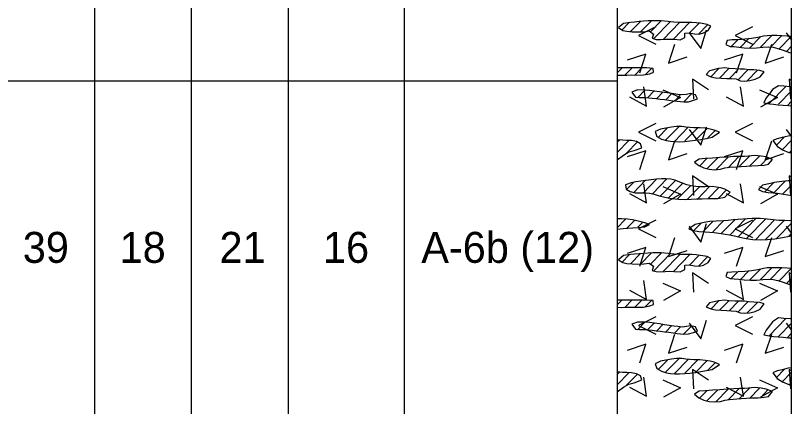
# Model space of a CAD drawing. Extents: x -0.01 to 0.83, y -0.63 to 1.27.
# Drawn here: x 0.6664 to 0.8333, y 0.5756 to 0.6598 of the extents above; entities that cross this region are included whole.
import ezdxf

# ---------------------------------------------------------------- set-up
doc = ezdxf.new("R2010")
doc.units = 0

msp = doc.modelspace()

# ---------------------------------------------------------------- linework, layer by layer
for points in [[(0, 0), (0.83333, 0), (0.83333, 1.275), (0, 1.275)], [(0, 0), (0.83333, 0), (0.83333, 1.275), (0, 1.275)], [(0, 0), (0.83333, 0), (0.83333, 1.275), (0, 1.275)], [(0, 0), (0.83333, 0), (0.83333, 1.275), (0, 1.275)], [(0, 0), (0.83333, 0), (0.83333, 1.275), (0, 1.275)], [(0.79708, 0.65659), (0.79794, 0.65641), (0.79904, 0.6563), (0.80028, 0.65627), (0.80156, 0.65632), (0.80274, 0.65648), (0.80361, 0.65582), (0.80338, 0.65492), (0.80422, 0.65465), (0.80517, 0.65463), (0.80613, 0.65469), (0.8072, 0.65472), (0.80818, 0.65469), (0.80939, 0.65461), (0.81037, 0.65508), (0.81038, 0.65603), (0.8113, 0.65609), (0.81244, 0.6559), (0.81346, 0.65579), (0.81438, 0.65605), (0.81539, 0.65659), (0.81601, 0.6575), (0.81517, 0.65788), (0.81374, 0.65815), (0.81285, 0.65825), (0.81187, 0.65831), (0.81, 0.65831), (0.8091, 0.65833), (0.808, 0.6584), (0.80678, 0.65856), (0.8053, 0.65869), (0.80443, 0.6587), (0.80349, 0.65868), (0.80251, 0.65864), (0.80152, 0.65858), (0.80054, 0.6585), (0.79959, 0.65841), (0.7987, 0.65831), (0.79722, 0.65809), (0.79614, 0.65721)], [(0.83241, 0.65537), (0.83129, 0.65544), (0.83017, 0.65548), (0.8291, 0.65548), (0.82811, 0.65544), (0.82728, 0.65535), (0.82608, 0.65505), (0.82476, 0.65483), (0.8233, 0.65469), (0.82183, 0.65461), (0.82051, 0.65455), (0.81951, 0.65445), (0.81922, 0.65358), (0.82013, 0.65316), (0.82097, 0.65311), (0.822, 0.65301), (0.82318, 0.65288), (0.82448, 0.6528), (0.82584, 0.65282), (0.82719, 0.65298), (0.82836, 0.65305), (0.8294, 0.65297), (0.83043, 0.65274), (0.83156, 0.65235), (0.83291, 0.65186), (0.83333, 0.65178), (0.83333, 0.6553)], [(0.79583, 0.64696), (0.79676, 0.64695), (0.79792, 0.64697), (0.79882, 0.64701), (0.79992, 0.64697), (0.80151, 0.64701), (0.80282, 0.64727), (0.80367, 0.64759), (0.80354, 0.64843), (0.80216, 0.64851), (0.79583, 0.64851)], [(0.81822, 0.64632), (0.81944, 0.64626), (0.82033, 0.64622), (0.82145, 0.64615), (0.82229, 0.64574), (0.82324, 0.64569), (0.82438, 0.6458), (0.82555, 0.64608), (0.82662, 0.64659), (0.82749, 0.64769), (0.82651, 0.64799), (0.82524, 0.64809), (0.82413, 0.64815), (0.82324, 0.64826), (0.82226, 0.64828), (0.82121, 0.6483), (0.81995, 0.64839), (0.81902, 0.64851), (0.81761, 0.64837), (0.81566, 0.64793), (0.81496, 0.64709), (0.81598, 0.6466), (0.81695, 0.64642)], [(0.83305, 0.64446), (0.83171, 0.64457), (0.83054, 0.64467), (0.82925, 0.64385), (0.82857, 0.64294), (0.82792, 0.64205), (0.82735, 0.64103), (0.82858, 0.6408), (0.82945, 0.6407), (0.83045, 0.6406), (0.83155, 0.64051), (0.83272, 0.64041), (0.83333, 0.64036), (0.83333, 0.64445)], [(0.80066, 0.64216), (0.80188, 0.64215), (0.80339, 0.64202), (0.80423, 0.64193), (0.8051, 0.64182), (0.806, 0.6417), (0.80692, 0.64158), (0.80784, 0.64146), (0.80875, 0.64135), (0.81014, 0.64121), (0.81119, 0.64122), (0.81222, 0.64157), (0.81308, 0.64185), (0.81267, 0.64275), (0.8116, 0.643), (0.81075, 0.6428), (0.80989, 0.64272), (0.80885, 0.6428), (0.80799, 0.64291), (0.80703, 0.64306), (0.806, 0.64322), (0.80492, 0.64339), (0.80384, 0.64354), (0.8028, 0.64367), (0.80182, 0.64377), (0.8002, 0.64378), (0.79901, 0.6433), (0.79974, 0.64226)], [(0.81233, 0.63565), (0.81063, 0.63577), (0.80977, 0.63591), (0.8086, 0.63591), (0.80755, 0.63577), (0.80632, 0.63557), (0.80513, 0.63533), (0.80403, 0.63481), (0.80436, 0.63375), (0.80536, 0.63318), (0.80647, 0.63288), (0.8073, 0.63273), (0.80824, 0.63265), (0.80926, 0.63264), (0.81035, 0.63269), (0.81149, 0.6328), (0.81267, 0.63294), (0.81386, 0.63313), (0.81506, 0.63334), (0.81625, 0.63358), (0.81783, 0.63466), (0.81673, 0.63515), (0.81585, 0.63536), (0.8148, 0.63552), (0.81361, 0.63562)], [(0.79583, 0.62875), (0.79719, 0.62974), (0.79831, 0.63044), (0.79951, 0.63071), (0.80111, 0.63131), (0.80086, 0.63219), (0.80002, 0.63267), (0.79889, 0.63286), (0.79791, 0.63289), (0.79694, 0.63295), (0.79583, 0.63303)], [(0.83265, 0.63384), (0.83136, 0.63353), (0.83028, 0.63326), (0.82934, 0.63286), (0.83026, 0.63166), (0.83142, 0.6309), (0.83279, 0.63032), (0.83333, 0.63022), (0.83333, 0.63393)], [(0.82537, 0.62969), (0.82408, 0.62954), (0.82319, 0.62948), (0.82214, 0.62946), (0.82091, 0.62942), (0.81947, 0.62933), (0.81792, 0.62921), (0.81632, 0.62909), (0.81475, 0.629), (0.81348, 0.62889), (0.81247, 0.62825), (0.81337, 0.62749), (0.81444, 0.62699), (0.81561, 0.6267), (0.81675, 0.6266), (0.81807, 0.62671), (0.81896, 0.62698), (0.82003, 0.62713), (0.82157, 0.62725), (0.82253, 0.62731), (0.82362, 0.62737), (0.82483, 0.62743), (0.82618, 0.62749), (0.82745, 0.6276), (0.82842, 0.62778), (0.82927, 0.62883), (0.82791, 0.62935), (0.82679, 0.62955)], [(0.79885, 0.62378), (0.79763, 0.62332), (0.79773, 0.62242), (0.79859, 0.6219), (0.7997, 0.6216), (0.80074, 0.62161), (0.80165, 0.62163), (0.80281, 0.62154), (0.80377, 0.62134), (0.80486, 0.62099), (0.80606, 0.62069), (0.80751, 0.62042), (0.80905, 0.62023), (0.81052, 0.6202), (0.81177, 0.62026), (0.81289, 0.6203), (0.81408, 0.62033), (0.81553, 0.62037), (0.81642, 0.6204), (0.81745, 0.62043), (0.81897, 0.6207), (0.82011, 0.62174), (0.81896, 0.62241), (0.8181, 0.62268), (0.81717, 0.62287), (0.81626, 0.62298), (0.81479, 0.62292), (0.81343, 0.62292), (0.8121, 0.62307), (0.8108, 0.62337), (0.80953, 0.62383), (0.8082, 0.62438), (0.80736, 0.62454), (0.8064, 0.62462), (0.80536, 0.62462), (0.80427, 0.62456), (0.80314, 0.62445), (0.80201, 0.62431), (0.8009, 0.62414), (0.79984, 0.62396)], [(0.83263, 0.62423), (0.83126, 0.62409), (0.82969, 0.62382), (0.82883, 0.62365), (0.82712, 0.62324), (0.82623, 0.62237), (0.82708, 0.62188), (0.82831, 0.62169), (0.82941, 0.62163), (0.83033, 0.62154), (0.83165, 0.62135), (0.83253, 0.62121), (0.83333, 0.62107), (0.83333, 0.62422)], [(0.82816, 0.61157), (0.82978, 0.61174), (0.83137, 0.612), (0.8329, 0.61231), (0.83333, 0.61241), (0.83333, 0.61565), (0.83295, 0.61562), (0.83188, 0.61564), (0.83071, 0.61569), (0.82938, 0.6158), (0.82807, 0.61597), (0.82662, 0.61608), (0.82576, 0.61609), (0.82484, 0.61606), (0.82387, 0.61601), (0.82286, 0.61594), (0.82182, 0.61586), (0.82077, 0.61578), (0.81973, 0.61569), (0.81872, 0.61562), (0.81715, 0.61552), (0.81579, 0.61543), (0.81491, 0.6153), (0.81357, 0.61502), (0.8126, 0.61481), (0.81121, 0.61389), (0.8121, 0.61353), (0.81345, 0.61328), (0.81479, 0.61319), (0.81668, 0.61309), (0.81818, 0.61289), (0.81905, 0.61275), (0.82, 0.61257), (0.82107, 0.61235), (0.82225, 0.6121), (0.82357, 0.61181), (0.82501, 0.61158), (0.82656, 0.61151)], [(0.79583, 0.61382), (0.79715, 0.61393), (0.79814, 0.61401), (0.79922, 0.61408), (0.80039, 0.61417), (0.80179, 0.61429), (0.80275, 0.6148), (0.80179, 0.61515), (0.80091, 0.61536), (0.80003, 0.61558), (0.79909, 0.61579), (0.79803, 0.61595), (0.79677, 0.61605), (0.79583, 0.61603)], [(0.79708, 0.60659), (0.79794, 0.60641), (0.79904, 0.6063), (0.80028, 0.60627), (0.80156, 0.60632), (0.80274, 0.60648), (0.80361, 0.60582), (0.80338, 0.60492), (0.80422, 0.60465), (0.80517, 0.60463), (0.80613, 0.60469), (0.8072, 0.60472), (0.80818, 0.60469), (0.80939, 0.60461), (0.81037, 0.60508), (0.81038, 0.60603), (0.8113, 0.60609), (0.81244, 0.6059), (0.81346, 0.60579), (0.81438, 0.60605), (0.81539, 0.60659), (0.81601, 0.6075), (0.81517, 0.60788), (0.81374, 0.60815), (0.81285, 0.60825), (0.81187, 0.60831), (0.81, 0.60831), (0.8091, 0.60833), (0.808, 0.6084), (0.80678, 0.60856), (0.8053, 0.60869), (0.80443, 0.6087), (0.80349, 0.60868), (0.80251, 0.60864), (0.80152, 0.60858), (0.80054, 0.6085), (0.79959, 0.60841), (0.7987, 0.60831), (0.79722, 0.60809), (0.79614, 0.60721)], [(0.83241, 0.60537), (0.83129, 0.60544), (0.83017, 0.60548), (0.8291, 0.60548), (0.82811, 0.60544), (0.82728, 0.60535), (0.82608, 0.60505), (0.82476, 0.60483), (0.8233, 0.60469), (0.82183, 0.60461), (0.82051, 0.60455), (0.81951, 0.60445), (0.81922, 0.60358), (0.82013, 0.60316), (0.82097, 0.60311), (0.822, 0.60301), (0.82318, 0.60288), (0.82448, 0.6028), (0.82584, 0.60282), (0.82719, 0.60298), (0.82836, 0.60305), (0.8294, 0.60297), (0.83043, 0.60274), (0.83156, 0.60235), (0.83291, 0.60186), (0.83333, 0.60178), (0.83333, 0.6053)], [(0.79583, 0.59696), (0.79676, 0.59695), (0.79792, 0.59697), (0.79882, 0.59701), (0.79992, 0.59697), (0.80151, 0.59701), (0.80282, 0.59727), (0.80367, 0.59759), (0.80354, 0.59843), (0.80216, 0.59851), (0.79583, 0.59851)], [(0.81822, 0.59632), (0.81944, 0.59626), (0.82033, 0.59622), (0.82145, 0.59615), (0.82229, 0.59574), (0.82324, 0.59569), (0.82438, 0.5958), (0.82555, 0.59608), (0.82662, 0.59659), (0.82749, 0.59769), (0.82651, 0.59799), (0.82524, 0.59809), (0.82413, 0.59815), (0.82324, 0.59826), (0.82226, 0.59828), (0.82121, 0.5983), (0.81995, 0.59839), (0.81902, 0.59851), (0.81761, 0.59837), (0.81566, 0.59793), (0.81496, 0.59709), (0.81598, 0.5966), (0.81695, 0.59642)], [(0.83305, 0.59446), (0.83171, 0.59457), (0.83054, 0.59467), (0.82925, 0.59385), (0.82857, 0.59294), (0.82792, 0.59205), (0.82735, 0.59103), (0.82858, 0.5908), (0.82945, 0.5907), (0.83045, 0.5906), (0.83155, 0.59051), (0.83272, 0.59041), (0.83333, 0.59036), (0.83333, 0.59445)], [(0.80066, 0.59216), (0.80188, 0.59215), (0.80339, 0.59202), (0.80423, 0.59193), (0.8051, 0.59182), (0.806, 0.5917), (0.80692, 0.59158), (0.80784, 0.59146), (0.80875, 0.59135), (0.81014, 0.59121), (0.81119, 0.59122), (0.81222, 0.59157), (0.81308, 0.59185), (0.81267, 0.59275), (0.8116, 0.593), (0.81075, 0.5928), (0.80989, 0.59272), (0.80885, 0.5928), (0.80799, 0.59291), (0.80703, 0.59306), (0.806, 0.59322), (0.80492, 0.59339), (0.80384, 0.59354), (0.8028, 0.59367), (0.80182, 0.59377), (0.8002, 0.59378), (0.79901, 0.5933), (0.79974, 0.59226)], [(0.81233, 0.58565), (0.81063, 0.58577), (0.80977, 0.58591), (0.8086, 0.58591), (0.80755, 0.58577), (0.80632, 0.58557), (0.80513, 0.58533), (0.80403, 0.58481), (0.80436, 0.58375), (0.80536, 0.58318), (0.80647, 0.58288), (0.8073, 0.58273), (0.80824, 0.58265), (0.80926, 0.58264), (0.81035, 0.58269), (0.81149, 0.5828), (0.81267, 0.58294), (0.81386, 0.58313), (0.81506, 0.58334), (0.81625, 0.58358), (0.81783, 0.58466), (0.81673, 0.58515), (0.81585, 0.58536), (0.8148, 0.58552), (0.81361, 0.58562)], [(0.79583, 0.57875), (0.79719, 0.57974), (0.79831, 0.58044), (0.79951, 0.58071), (0.80111, 0.58131), (0.80086, 0.58219), (0.80002, 0.58267), (0.79889, 0.58286), (0.79791, 0.58289), (0.79694, 0.58295), (0.79583, 0.58303)], [(0.83265, 0.58384), (0.83136, 0.58353), (0.83028, 0.58326), (0.82934, 0.58286), (0.83026, 0.58166), (0.83142, 0.5809), (0.83279, 0.58032), (0.83333, 0.58022), (0.83333, 0.58393)], [(0.82537, 0.57969), (0.82408, 0.57954), (0.82319, 0.57948), (0.82214, 0.57946), (0.82091, 0.57942), (0.81947, 0.57933), (0.81792, 0.57921), (0.81632, 0.57909), (0.81475, 0.579), (0.81348, 0.57889), (0.81247, 0.57825), (0.81337, 0.57749), (0.81444, 0.57699), (0.81561, 0.5767), (0.81675, 0.5766), (0.81807, 0.57671), (0.81896, 0.57698), (0.82003, 0.57713), (0.82157, 0.57725), (0.82253, 0.57731), (0.82362, 0.57737), (0.82483, 0.57743), (0.82618, 0.57749), (0.82745, 0.5776), (0.82842, 0.57778), (0.82927, 0.57883), (0.82791, 0.57935), (0.82679, 0.57955)]]:
    msp.add_lwpolyline(points, close=True)
for points in [[(0.725, 1.22083), (0.725, -0.62183)], [(0.75, 1.22083), (0.75, -0.62183)], [(0.75, 1.22083), (0.75, -0.62183)], [(0.79583, 1.22083), (0.79583, -0.62183)], [(0.68333, 1.20833), (0.68333, -0.62183)], [(0.70417, 1.20833), (0.70417, -0.62183)], [(0.725, 1.20833), (0.725, -0.62183)], [(0.83333, -0.62183), (0.83333, 1.13843)], [(0.79844, 0.65828), (0.79691, 0.65671)], [(0.79871, 0.65634), (0.80085, 0.65853)], [(0.80083, 0.65629), (0.80311, 0.65863)], [(0.80534, 0.65871), (0.80299, 0.65629)], [(0.80367, 0.65478), (0.80732, 0.65852)], [(0.80571, 0.65466), (0.80924, 0.65828)], [(0.81142, 0.65829), (0.80785, 0.65464)], [(0.81141, 0.65607), (0.81348, 0.65819)], [(0.81528, 0.65783), (0.81331, 0.65581)], [(0.80412, 0.65741), (0.80038, 0.65554), (0.80412, 0.65366)], [(0.81134, 0.65607), (0.81384, 0.6527), (0.81503, 0.6567)], [(0.82496, 0.65741), (0.82121, 0.65554), (0.82496, 0.65366)], [(0.82035, 0.65315), (0.82176, 0.6546)], [(0.82233, 0.65298), (0.82408, 0.65476)], [(0.82433, 0.65281), (0.82666, 0.6552)], [(0.82909, 0.65548), (0.82656, 0.65289)], [(0.82885, 0.65301), (0.83122, 0.65544)], [(0.83325, 0.65531), (0.83065, 0.65265)], [(0.83217, 0.65607), (0.83333, 0.65451)], [(0.80818, 0.65358), (0.80687, 0.64958), (0.81087, 0.65089)], [(0.82901, 0.65358), (0.8277, 0.64958), (0.8317, 0.65089)], [(0.83333, 0.65318), (0.83227, 0.65209)], [(0.80069, 0.6475), (0.802, 0.6515), (0.798, 0.65019)], [(0.82152, 0.6475), (0.82284, 0.6515), (0.81884, 0.65019)], [(0.79583, 0.64748), (0.79681, 0.64848)], [(0.79898, 0.6485), (0.79747, 0.64695)], [(0.80116, 0.64852), (0.79959, 0.64691)], [(0.80328, 0.64848), (0.80188, 0.64704)], [(0.8177, 0.64837), (0.81596, 0.64659)], [(0.81988, 0.64839), (0.81785, 0.64632)], [(0.82185, 0.6482), (0.81997, 0.64627)], [(0.824, 0.64819), (0.82178, 0.64591)], [(0.82601, 0.64803), (0.82378, 0.64575)], [(0.6625, 0.64575), (0.68333, 0.64575)], [(0.68333, 0.64575), (0.70417, 0.64575)], [(0.70417, 0.64575), (0.725, 0.64575)], [(0.725, 0.64575), (0.75, 0.64575)], [(0.75, 0.64575), (0.79583, 0.64575)], [(0.81551, 0.64378), (0.81201, 0.64609), (0.81226, 0.6419)], [(0.83217, 0.64459), (0.82844, 0.64077)], [(0.83333, 0.64577), (0.83284, 0.64609), (0.83309, 0.6419)], [(0.79847, 0.64229), (0.80215, 0.64029), (0.80153, 0.64442)], [(0.80188, 0.64381), (0.8002, 0.64209)], [(0.8038, 0.64357), (0.80237, 0.64211)], [(0.80575, 0.64335), (0.80429, 0.64186)], [(0.80562, 0.64384), (0.80946, 0.64215), (0.80581, 0.64009)], [(0.80758, 0.64302), (0.80627, 0.64167)], [(0.81188, 0.643), (0.81016, 0.64124)], [(0.8193, 0.64229), (0.82299, 0.64029), (0.82236, 0.64442)], [(0.82645, 0.64384), (0.83029, 0.64215), (0.82664, 0.64009)], [(0.83333, 0.64357), (0.83052, 0.64069)], [(0.80941, 0.64269), (0.80816, 0.6414)], [(0.83333, 0.64136), (0.83245, 0.64045)], [(0.80412, 0.63658), (0.80038, 0.63471), (0.80412, 0.63283)], [(0.82496, 0.63658), (0.82121, 0.63471), (0.82496, 0.63283)], [(0.80465, 0.63354), (0.80667, 0.63561)], [(0.80626, 0.63297), (0.80928, 0.63607)], [(0.80809, 0.63264), (0.81111, 0.63573)], [(0.81041, 0.6328), (0.81318, 0.63564)], [(0.81134, 0.63524), (0.81384, 0.63186), (0.81503, 0.63586)], [(0.81264, 0.63288), (0.81518, 0.63548)], [(0.81536, 0.63345), (0.81699, 0.63511)], [(0.83217, 0.63524), (0.83333, 0.63368)], [(0.7963, 0.63299), (0.79583, 0.63251)], [(0.79834, 0.63286), (0.79583, 0.6303)], [(0.8301, 0.63187), (0.83184, 0.63366)], [(0.83131, 0.6309), (0.83333, 0.63298)], [(0.79786, 0.63016), (0.80023, 0.63259)], [(0.80818, 0.63275), (0.80687, 0.62875), (0.81087, 0.63006)], [(0.82901, 0.63275), (0.8277, 0.62875), (0.8317, 0.63006)], [(0.80069, 0.62667), (0.802, 0.63067), (0.798, 0.62936)], [(0.82152, 0.62667), (0.82284, 0.63067), (0.81884, 0.62936)], [(0.82202, 0.6272), (0.8243, 0.62954)], [(0.82431, 0.62733), (0.82644, 0.62953)], [(0.83285, 0.63027), (0.83333, 0.63076)], [(0.81519, 0.62906), (0.81354, 0.62736)], [(0.81514, 0.6268), (0.81748, 0.62919)], [(0.81709, 0.62658), (0.81974, 0.6293)], [(0.8197, 0.62703), (0.82203, 0.62943)], [(0.82663, 0.6275), (0.82834, 0.62925)], [(0.80142, 0.62158), (0.8043, 0.62453)], [(0.80653, 0.62461), (0.8034, 0.6214)], [(0.81551, 0.62294), (0.81201, 0.62525), (0.81226, 0.62107)], [(0.83333, 0.62493), (0.83284, 0.62525), (0.83309, 0.62107)], [(0.79938, 0.62392), (0.79786, 0.62237)], [(0.79847, 0.62146), (0.80215, 0.61946), (0.80153, 0.62358)], [(0.79933, 0.62165), (0.80195, 0.62434)], [(0.80506, 0.62089), (0.8084, 0.62431)], [(0.80562, 0.623), (0.80946, 0.62132), (0.80581, 0.61926)], [(0.80997, 0.62371), (0.80675, 0.6204)], [(0.81164, 0.6232), (0.80884, 0.62034)], [(0.81353, 0.62293), (0.81094, 0.62027)], [(0.81303, 0.62021), (0.81579, 0.62303)], [(0.8193, 0.62146), (0.82299, 0.61946), (0.82236, 0.62358)], [(0.82645, 0.623), (0.83029, 0.62132), (0.82664, 0.61926)], [(0.82751, 0.62176), (0.82945, 0.62375)], [(0.83203, 0.62417), (0.82949, 0.62157)], [(0.83138, 0.6213), (0.83333, 0.6233)], [(0.81534, 0.62036), (0.81768, 0.62276)], [(0.8176, 0.62047), (0.81934, 0.62225)], [(0.83333, 0.62108), (0.83333, 0.62109)], [(0.79765, 0.61594), (0.79583, 0.61407)], [(0.7996, 0.61572), (0.79786, 0.61394)], [(0.8013, 0.61524), (0.80027, 0.61419)], [(0.80412, 0.61575), (0.80038, 0.61387), (0.80412, 0.612)], [(0.81134, 0.61441), (0.81384, 0.61103), (0.81503, 0.61503)], [(0.81392, 0.61508), (0.81235, 0.61348)], [(0.8143, 0.61326), (0.8165, 0.61551)], [(0.8164, 0.61319), (0.81879, 0.61564)], [(0.81829, 0.61291), (0.82114, 0.61584)], [(0.82004, 0.61249), (0.82346, 0.616)], [(0.82496, 0.61575), (0.82121, 0.61387), (0.82496, 0.612)], [(0.82569, 0.61608), (0.82184, 0.61213)], [(0.82775, 0.61598), (0.8237, 0.61183)], [(0.82964, 0.6157), (0.82557, 0.61152)], [(0.83173, 0.61563), (0.82774, 0.61154)], [(0.83333, 0.61506), (0.83012, 0.61176)], [(0.83217, 0.61441), (0.83333, 0.61284)], [(0.83281, 0.61231), (0.83333, 0.61284)], [(0.80818, 0.61192), (0.80687, 0.60792), (0.81087, 0.60923)], [(0.82901, 0.61192), (0.8277, 0.60792), (0.8317, 0.60923)], [(0.80069, 0.60583), (0.802, 0.60983), (0.798, 0.60852)], [(0.82152, 0.60583), (0.82284, 0.60983), (0.81884, 0.60852)], [(0.79844, 0.60828), (0.79691, 0.60671)], [(0.79871, 0.60634), (0.80085, 0.60853)], [(0.80083, 0.60629), (0.80311, 0.60863)], [(0.80534, 0.60871), (0.80299, 0.60629)], [(0.80367, 0.60478), (0.80732, 0.60852)], [(0.80571, 0.60466), (0.80924, 0.60828)], [(0.81142, 0.60829), (0.80785, 0.60464)], [(0.81141, 0.60607), (0.81348, 0.60819)], [(0.81528, 0.60783), (0.81331, 0.60581)], [(0.81551, 0.60211), (0.81201, 0.60442), (0.81226, 0.60023)], [(0.82035, 0.60315), (0.82176, 0.6046)], [(0.82233, 0.60298), (0.82408, 0.60476)], [(0.82433, 0.60281), (0.82666, 0.6052)], [(0.82909, 0.60548), (0.82656, 0.60289)], [(0.82885, 0.60301), (0.83122, 0.60544)], [(0.83325, 0.60531), (0.83065, 0.60265)], [(0.83333, 0.6041), (0.83284, 0.60442), (0.83309, 0.60023)], [(0.79847, 0.60063), (0.80215, 0.59863), (0.80153, 0.60275)], [(0.8193, 0.60063), (0.82299, 0.59863), (0.82236, 0.60275)], [(0.83333, 0.60318), (0.83227, 0.60209)], [(0.80562, 0.60217), (0.80946, 0.60049), (0.80581, 0.59843)], [(0.82645, 0.60217), (0.83029, 0.60049), (0.82664, 0.59843)], [(0.79583, 0.59748), (0.79681, 0.59848)], [(0.79898, 0.5985), (0.79747, 0.59695)], [(0.80116, 0.59852), (0.79959, 0.59691)], [(0.80328, 0.59848), (0.80188, 0.59704)], [(0.8177, 0.59837), (0.81596, 0.59659)], [(0.81988, 0.59839), (0.81785, 0.59632)], [(0.82185, 0.5982), (0.81997, 0.59627)], [(0.824, 0.59819), (0.82178, 0.59591)], [(0.82601, 0.59803), (0.82378, 0.59575)], [(0.80412, 0.59491), (0.80038, 0.59304), (0.80412, 0.59116)], [(0.82496, 0.59491), (0.82121, 0.59304), (0.82496, 0.59116)], [(0.83217, 0.59459), (0.82844, 0.59077)], [(0.80188, 0.59381), (0.8002, 0.59209)], [(0.8038, 0.59357), (0.80237, 0.59211)], [(0.80575, 0.59335), (0.80429, 0.59186)], [(0.80758, 0.59302), (0.80627, 0.59168)], [(0.81188, 0.593), (0.81016, 0.59124)], [(0.81134, 0.59357), (0.81384, 0.5902), (0.81503, 0.5942)], [(0.83333, 0.59357), (0.83052, 0.59069)], [(0.83217, 0.59357), (0.83333, 0.59201)], [(0.80818, 0.59108), (0.80687, 0.58708), (0.81087, 0.58839)], [(0.80941, 0.59269), (0.80816, 0.5914)], [(0.82901, 0.59108), (0.8277, 0.58708), (0.8317, 0.58839)], [(0.83333, 0.59136), (0.83245, 0.59045)], [(0.80069, 0.585), (0.802, 0.589), (0.798, 0.58769)], [(0.82152, 0.585), (0.82284, 0.589), (0.81884, 0.58769)], [(0.80626, 0.58297), (0.80928, 0.58607)], [(0.80465, 0.58354), (0.80667, 0.58561)], [(0.80809, 0.58264), (0.81111, 0.58573)], [(0.81041, 0.5828), (0.81318, 0.58564)], [(0.81264, 0.58288), (0.81518, 0.58548)], [(0.81536, 0.58345), (0.81699, 0.58511)], [(0.7963, 0.58299), (0.79583, 0.58251)], [(0.79834, 0.58286), (0.79583, 0.5803)], [(0.81551, 0.58128), (0.81201, 0.58359), (0.81226, 0.5794)], [(0.8301, 0.58187), (0.83184, 0.58366)], [(0.83131, 0.5809), (0.83333, 0.58298)], [(0.83333, 0.58327), (0.83284, 0.58359), (0.83309, 0.5794)], [(0.79786, 0.58016), (0.80023, 0.58259)], [(0.79847, 0.57979), (0.80215, 0.57779), (0.80153, 0.58192)], [(0.80562, 0.58134), (0.80946, 0.57965), (0.80581, 0.57759)], [(0.8193, 0.57979), (0.82299, 0.57779), (0.82236, 0.58192)], [(0.82645, 0.58134), (0.83029, 0.57965), (0.82664, 0.57759)], [(0.8197, 0.57703), (0.82203, 0.57943)], [(0.82202, 0.5772), (0.8243, 0.57954)], [(0.82431, 0.57733), (0.82644, 0.57953)], [(0.83285, 0.58027), (0.83333, 0.58076)], [(0.81519, 0.57906), (0.81354, 0.57736)], [(0.81514, 0.5768), (0.81748, 0.57919)], [(0.81709, 0.57658), (0.81974, 0.5793)], [(0.82663, 0.5775), (0.82834, 0.57925)]]:
    msp.add_lwpolyline(points)

# ---------------------------------------------------------------- texts
for s, p in [('39', (0.66794, 0.60654)), ('18', (0.68878, 0.60654)), ('21', (0.71026, 0.60654)), ('16', (0.73253, 0.60654)), ('A-6b (12)', (0.75368, 0.60654))]:
    msp.add_text(s, height=0.006667).set_placement(p)

doc.saveas('drawing.dxf')
